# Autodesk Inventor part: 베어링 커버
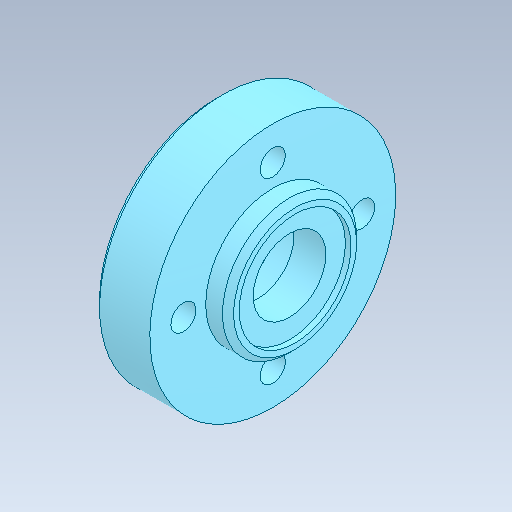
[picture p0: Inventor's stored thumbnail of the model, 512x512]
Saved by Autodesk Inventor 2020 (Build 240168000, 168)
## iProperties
Created: 2024-07
Part Number: 베어링 커버
Material: 강철, 연강
Document SubType Name: Modeling
Designer: oem
Density: 7.85 g/cm^3
Appearance: 기본값
Author: jhkim
Sending System: Autodesk Inventor 2025
Preprocessor: ST-DEVELOPER v20
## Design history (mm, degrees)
feature "솔리드1"
node "솔리드2"
